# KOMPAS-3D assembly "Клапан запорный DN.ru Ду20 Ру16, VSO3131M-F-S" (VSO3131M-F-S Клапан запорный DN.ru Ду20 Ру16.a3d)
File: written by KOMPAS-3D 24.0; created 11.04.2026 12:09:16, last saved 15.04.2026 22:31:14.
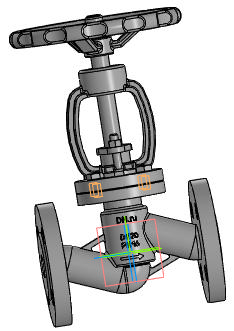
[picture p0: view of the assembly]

Document properties: Автор: R2D2; Полное имя файла: E:\Работа\Зайцев\VSO3131M-F-S Клапан запорный DN.ru Ду15-100 Ру16\DN20\исходные материалы\VSO3131M-F-S Клапан запорный DN.ru Ду20 Ру16.a3d

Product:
- Component [detail]: Корпус  | qty 1  | pos. 1  | Масса: 6.9; Автор: R2D2; source file: Корпус.m3d
- Component [detail]: Сборка  | qty 1  | pos. 2  | Масса: 1.44705; Автор: R2D2; source file: 2.m3d
- Body: Тело 2  | qty 1
    Масса: 1.42711
- Component [standard]: Hexagon head screw ISO 4017 - М8 x 16  | qty 4  | Масса: 0.012085; Раздел спецификации: Стандартные изделия; Рассекать на разрезах: no
- Part/product: Клапан запорный DN.ru Ду20 Ру16  | designation VSO3131M-F-S
    Масса: 4.05
    Раздел спецификации: Прочие изделия
    Примечание: D090-02947

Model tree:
1. Эскиз:2  (with: Ребро.Элемент вращения:2, Ребро.Операция без истории:1, Грань.Элемент вращения:2)
2. Элемент вращения:1
     Угол 1 = 360
3. Эскиз:3  (with: Ребро.Операция без истории:1)
4. Элемент выдавливания:2
     Расстояние 1 = 27
5. Зеркальный массив:1
6. Экземпляр ( 1 )
7. Экземпляр ( 2 )  (with: Элемент выдавливания:2)
8. Массив по концентрической сетке:1  (with: Грань.Элемент вращения:2, Грань.Операция без истории:1)  (labels: Грань.Элемент выдавливания:9.Экземпляр ( 1, 2 ); Труба@/Нестандартная труба@/L = 73.6 мм; Труба@/Нестандартная труба@/L = 89.3 мм)  (4 pattern instances)
     Шаг 2 = 360; Расстояние = -200

Referenced files in E:\Работа\Зайцев\VSO3131M-F-S Клапан запорный DN.ru Ду15-100 Ру40\DN20\исходные материалы\: Корпус.m3d, 2.m3d
Referenced files in E:\Работа\Зайцев\VSO3131M-F-S Клапан запорный DN.ru Ду15-100 Ру16\DN20\исходные материалы\: Корпус.m3d, 2.m3d
Referenced files in C:\Program Files\ASCON\KOMPAS-3D v24\Libs\PolynomLib\DATA\vault\Methods\Kompas\3D\: PLib_Bolt_1_ISO_1100.m3d
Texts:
  Hexagon head screw
  BOSimple***PART:17775d1c-e7de-f283-40f0-d40789f7f59e***SHORTLOC:A259_7B16EF33AB1642D2[13;1,25;16;8;-;Undefined]
  Программные изделия  и базы данных
  VSO3131M-F-S
  Hexagon head screw ISO 4017 - М8 x 16 (1)
  hole1
  hole2
  Ось Z.Начало координат
  Ось Y.Начало координат
  Плоскость XY.Начало координат
  Плоскость ZY.Начало координат
  Плоскость ZX.Начало координат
